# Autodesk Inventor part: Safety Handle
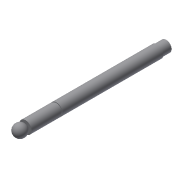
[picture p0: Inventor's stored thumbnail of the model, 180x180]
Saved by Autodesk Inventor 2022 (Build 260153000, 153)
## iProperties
Created: 2002-02
Part Number: Safety Handle
Document SubType Name: Modeling
Designer: ***
Density: 1 g/cm^3
Material: Generic
Appearance: Default
Control State: 0
Master: False
Checked Out: False
Shininess: 77.0
Length Units: 11269
Angle Units: 11279
Time Units: 11290
Mass Units: 11283
Length Display Precision: 3
Angle Display Precision: 2
Density: 0.0
Volumn: 0.0
Area: 0.0
PropertySet Name: Model Information
Author: ***
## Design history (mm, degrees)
sketch "Sketch1"
  geometry: L1 (0, 205)-(8, 205); L2 (8, 205)-(8, 192); L3 (8, 192)-(9, 192); L4 (9, 192)-(9, 45); L5 (9, 45)-(8, 45); L6 (8, 45)-(8, 43); L7 (8, 43)-(9, 43); L8 (9, 43)-(9, 0); L9 (9, 0)-(0, 0); L10 (0, 0)-(0, 205)
  constraints: 20 end point, 7 parallel, 1 collinear, 1 horizontal, 1 perpendicular
  dimensions: "d0" = 13 distance of L1.end L2.end; "d1" = 2 distance of L4.end L7.end; "d2" = 43 distance of L7.end L8.end; "d3" = 205 distance of L9.end L1.start; "d4" = 16 diameter of L2 L10; "d5" = 18 diameter of L4 L10; "d6" = 16 diameter of L6.end L10
revolve "Revolution1" sketch "Sketch1" stored, may be unused: angle "d7" = 90 deg
sketch "Sketch2"
  geometry: L1 (0, 1)-(0, -17); L2 (-9, 0)-(9, 0) reference; A1 r 9 centre (0, -8) between (0, -17) and (0, 1)
  constraints: 2 end point, 2 point on circle, 1 centre point, 1 midpoint, 1 vertical
  dimensions: "d8" = 9 radius of A1; "d9" = 1 distance from line of L2 L1.start
revolve "Revolution2" sketch "Sketch2" stored, may be unused: angle "d10" = 90 deg
body "Solid1"
